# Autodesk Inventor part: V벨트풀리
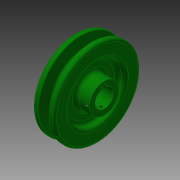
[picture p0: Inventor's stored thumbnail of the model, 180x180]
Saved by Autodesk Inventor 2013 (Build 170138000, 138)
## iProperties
Created: 2015-11
Part Number: V벨트풀리
Material: 강철, 탄소
Document SubType Name: Modeling
Designer: mduedu
Density: 1 g/cm^3
Author: mduedu
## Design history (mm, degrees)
sketch "스케치1"
  geometry: L1 (-9.5, 0)-(9.5, 0); L2 (0, 0)-(0, 37.7); L3 (-4.825, 37.7)-(-9.5, 37.7); L4 (-9.5, 37.7)-(-9.5, 0); L5 (0, 28.7)-(-2.074, 28.7); L6 (-2.074, 28.7)-(-4.825, 37.7); L7 (4.825, 37.7)-(9.5, 37.7); L8 (9.5, 37.7)-(9.5, 0); L9 (0, 28.7)-(2.074, 28.7); L10 (2.074, 28.7)-(4.825, 37.7); L11 (-9.5, 35)-(9.5, 35); 3 further points
  constraints: 22 end point, 7 point on line, 4 perpendicular, 3 symmetric about line, 1 coincident, 1 horizontal, 1 horizontal alignment, 1 midpoint, 1 vertical
  dimensions: "d0" = 19 distance of L1.start L1.end; "d2" = 75.4 diameter of L2.end L1 (derived); "d3" = 34 deg angle of L10 L6; "d4" = 6.3 distance between parallel lines of L11 L9; "d5" = 2.7 distance between parallel lines of L7 L11; "d6" = 8 distance of point (4, 35) point (-4, 35); "d7" = 70 diameter of L11 L1
revolve "회전1" sketch "스케치1" stored, may be unused: angle "d8" = 90 deg
sketch "스케치2"
  geometry: C1 r 24 at (0, 0); C2 r 13 at (0, 0); 1 further point
  constraints: 2 centre point, 2 coincident
  dimensions: "d9" = 48 diameter of C1; "d10" = 26 diameter of C2
extrude "돌출1" cut sketch "스케치2" distance "d11" = 6; taper "d12" = 0 deg
extrude "돌출3" join sketch "스케치2" distance "d37" = 6; taper "d38" = 0 deg
fillet "모깎기1" dims "d13" = 3
fillet "모깎기2" dims "d14" = 3
fillet "모깎기3" dims "d15" = 1, "d16" = 0.5, "d17" = 2
hole "구멍1" diameter "d20" = 16; stored, may be unused: countersink angle "d24" = 90 deg, drill point angle "d26" = 118 deg; dims "d21" = 6, "d22" = 4, "d23" = 2, "d25" = 8, "d53" = 10, "d54" = 10
sketch "스케치3"
  geometry: L1 (-2.5, 0)-(2.5, 0); L2 (2.5, 0)-(2.5, 10.3); L3 (2.5, 10.3)-(-2.5, 10.3); L4 (-2.5, 10.3)-(-2.5, 0); 2 further points
  constraints: 8 end point, 2 parallel, 1 coincident, 1 horizontal, 1 midpoint, 1 perpendicular
  dimensions: "d27" = 5 distance of L2.end L3.end; "d29" = 10.3 distance of L3.end L1.start
extrude "돌출2" cut sketch "스케치3" stored distance "d30" = 6; taper "d31" = 0 deg
node "작업 평면1"
sketch "스케치4"
  geometry: L1 (19, -27)-(19, 27) reference; 2 further points
  constraints: 1 horizontal alignment
  dimensions: "d52" = 22 distance from line of L1 point (-3, 0)
hole "구멍2" sketch "스케치4" at (-3, 0) diameter "d42" = 2.459; stored, may be unused: countersink angle "d46" = 90 deg, drill point angle "d48" = 118 deg; dims "d43" = 6, "d44" = 4, "d45" = 2, "d47" = 8
node "솔리드1"
mirror "대칭1"
pattern_circular "원형 패턴1" dims angle "d62" = 90 deg
